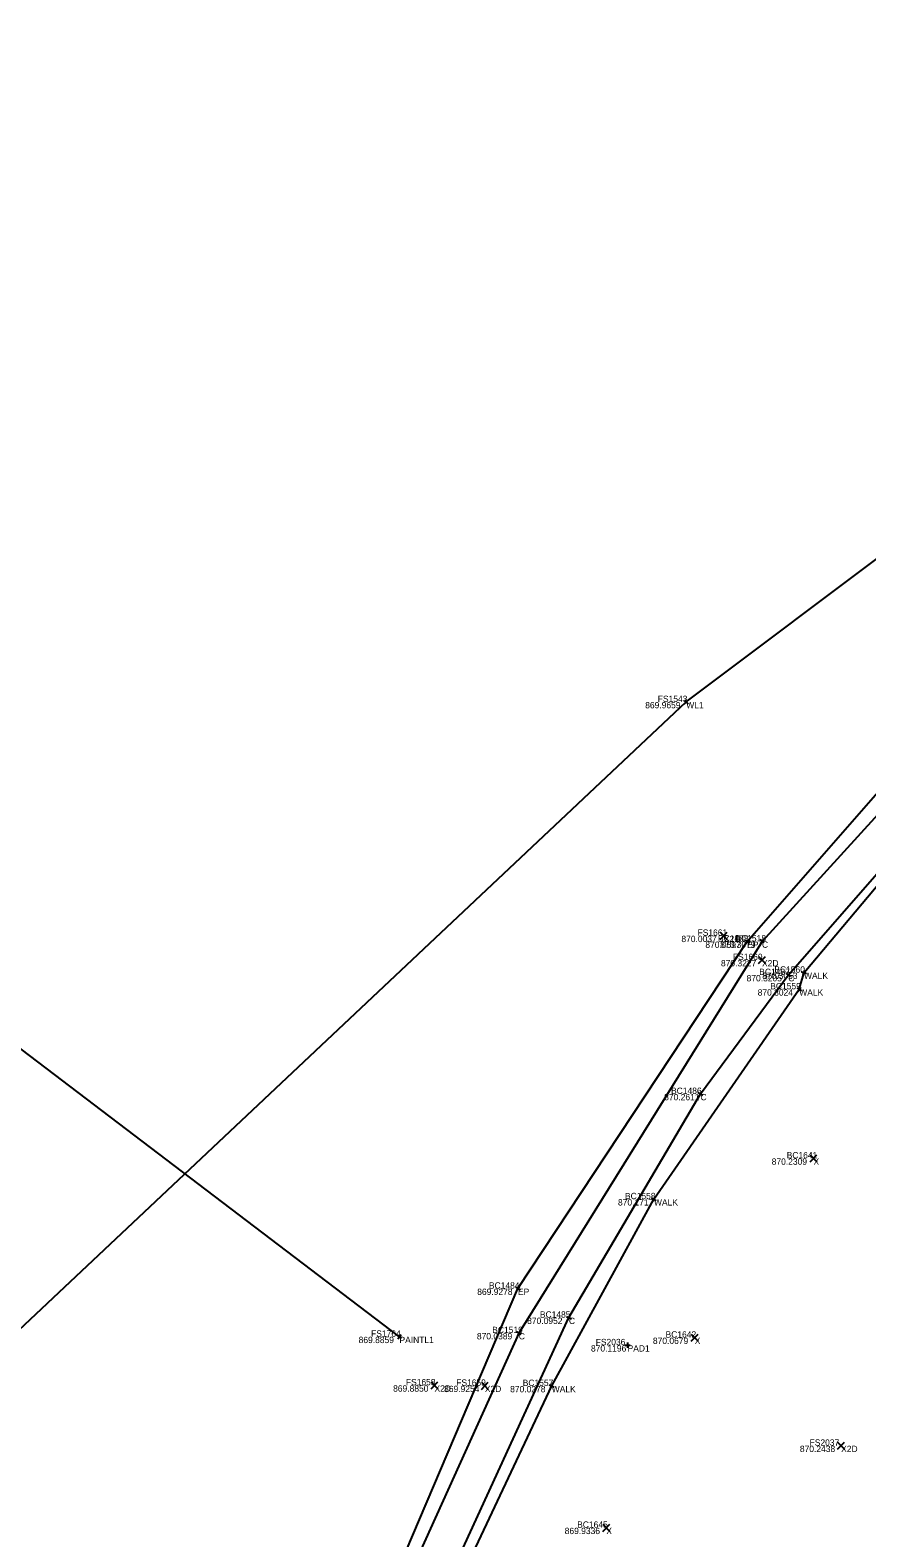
# Model space of a CAD drawing. Extents: x 1479425 to 1480294, y 379351 to 380102.
# Drawn here: x 1479693.48 to 1479701.41, y 379921.85 to 379936.13 of the extents above; entities that cross this region are included whole.
import ezdxf

# ---------------------------------------------------------------- set-up
doc = ezdxf.new("R2010")
doc.units = 0
for name, color, linetype in [('PM_X_Crosswalk', 7, 'Continuous'), ('PV_X_Curb', 7, 'Continuous'), ('PV_X_Walk', 7, 'Continuous'), ('SV_X_Random_Point', 7, 'Continuous'), ('SV_X_Shot_Marker', 7, 'Continuous'), ('SV_X_Text_Comment', 7, 'Continuous'), ('SV_X_Text_Elevation', 7, 'Continuous'), ('SV_X_Text_Name', 7, 'Continuous'), ('UT_X_Water', 7, 'Continuous')]:
    doc.layers.add(name, color=color, linetype=linetype)

msp = doc.modelspace()

# ---------------------------------------------------------------- linework, layer by layer
at = {"layer": 'PM_X_Crosswalk'}
msp.add_lwpolyline([(1479696.985, 379923.758), (1479671.854, 379942.855)], dxfattribs=at)
at = {"layer": 'PV_X_Curb'}
for points in [[(1479696.264, 379903.539), (1479695.57, 379906.746), (1479695.297, 379909.341), (1479695.174, 379911.646), (1479695.365, 379914.612), (1479695.698, 379917.667), (1479696.262, 379919.569), (1479696.976, 379921.561), (1479698.108, 379924.214), (1479700.28, 379927.501), (1479703.025, 379930.637), (1479705.95, 379933.539), (1479706.943, 379934.379), (1479708.075, 379934.808), (1479711.183, 379937.553), (1479719.99, 379942.117), (1479736.739, 379950.532), (1479753.296, 379958.795), (1479766.716, 379965.563), (1479785.836, 379974.829), (1479802.25, 379983.054), (1479831.407, 379997.252)], [(1479714.562, 379931.597), (1479714.954, 379931.846), (1479713.923, 379933.146), (1479712.281, 379934.169), (1479710.424, 379934.773), (1479708.769, 379934.79), (1479708.11, 379934.798), (1479707.065, 379934.215), (1479706.4, 379933.843), (1479705.682, 379933.059), (1479703.005, 379930.335), (1479700.421, 379927.502), (1479698.116, 379923.793), (1479697.054, 379921.447), (1479696.317, 379919.513), (1479695.811, 379917.681), (1479695.461, 379914.266), (1479695.292, 379911.66), (1479695.283, 379911.471), (1479695.51, 379908.764), (1479695.652, 379906.806)], [(1479696.734, 379903.723), (1479696.078, 379906.871), (1479695.857, 379909.367), (1479695.679, 379911.575), (1479695.63, 379911.718), (1479695.729, 379913.104), (1479695.978, 379915.675), (1479696.198, 379917.494), (1479696.642, 379919.385), (1479697.412, 379921.373), (1479698.591, 379923.939), (1479699.838, 379926.058), (1479700.67, 379927.184), (1479703.372, 379930.269), (1479706.251, 379933.059), (1479706.672, 379933.535), (1479707.045, 379933.739), (1479707.413, 379933.924), (1479708.304, 379934.333), (1479710.149, 379934.374), (1479711.615, 379933.931), (1479713.621, 379932.885), (1479714.299, 379932.035), (1479714.562, 379931.597)]]:
    msp.add_lwpolyline(points, dxfattribs=at)
at = {"layer": 'PV_X_Walk'}
msp.add_lwpolyline([(1479697.529, 379921.382), (1479698.428, 379923.292), (1479699.397, 379925.061), (1479700.774, 379927.049), (1479700.819, 379927.207), (1479702.519, 379929.228)], dxfattribs=at)
at = {"layer": 'SV_X_Random_Point'}
for p, q in [((1479700.026, 379927.522), (1479700.092, 379927.589)), ((1479700.026, 379927.589), (1479700.092, 379927.522)), ((1479700.388, 379927.293), (1479700.454, 379927.36)), ((1479700.388, 379927.36), (1479700.454, 379927.293)), ((1479700.876, 379925.414), (1479700.942, 379925.481)), ((1479700.876, 379925.481), (1479700.942, 379925.414)), ((1479699.749, 379923.717), (1479699.816, 379923.783)), ((1479699.749, 379923.783), (1479699.816, 379923.717)), ((1479697.284, 379923.264), (1479697.35, 379923.331)), ((1479697.284, 379923.331), (1479697.35, 379923.264)), ((1479697.761, 379923.26), (1479697.827, 379923.327)), ((1479697.761, 379923.327), (1479697.827, 379923.26)), ((1479701.138, 379922.693), (1479701.204, 379922.759)), ((1479701.138, 379922.759), (1479701.204, 379922.693)), ((1479698.912, 379921.915), (1479698.978, 379921.982)), ((1479698.912, 379921.982), (1479698.978, 379921.915))]:
    msp.add_line(p, q, dxfattribs=at)
at = {"layer": 'SV_X_Shot_Marker'}
for p, q in [((1479699.685, 379929.753), (1479699.721, 379929.788)), ((1479699.686, 379929.789), (1479699.72, 379929.752)), ((1479699.703, 379929.77), (1479699.703, 379929.77)), ((1479700.261, 379927.518), (1479700.299, 379927.485)), ((1479700.263, 379927.482), (1479700.296, 379927.52)), ((1479700.28, 379927.501), (1479700.28, 379927.501)), ((1479700.439, 379927.485), (1479700.402, 379927.519)), ((1479700.438, 379927.52), (1479700.404, 379927.483)), ((1479700.421, 379927.502), (1479700.421, 379927.502)), ((1479700.65, 379927.199), (1479700.69, 379927.169)), ((1479700.655, 379927.164), (1479700.685, 379927.204)), ((1479700.67, 379927.184), (1479700.67, 379927.184)), ((1479700.795, 379927.214), (1479700.843, 379927.2)), ((1479700.812, 379927.183), (1479700.826, 379927.231)), ((1479700.819, 379927.207), (1479700.819, 379927.207)), ((1479700.754, 379927.063), (1479700.795, 379927.035)), ((1479700.76, 379927.029), (1479700.789, 379927.07)), ((1479700.774, 379927.049), (1479700.774, 379927.049)), ((1479699.816, 379926.07), (1479699.86, 379926.045)), ((1479699.825, 379926.036), (1479699.851, 379926.079)), ((1479699.838, 379926.058), (1479699.838, 379926.058)), ((1479699.375, 379925.073), (1479699.419, 379925.049)), ((1479699.385, 379925.039), (1479699.409, 379925.083)), ((1479699.397, 379925.061), (1479699.397, 379925.061)), ((1479698.087, 379924.227), (1479698.129, 379924.2)), ((1479698.094, 379924.193), (1479698.122, 379924.234)), ((1479698.108, 379924.214), (1479698.108, 379924.214)), ((1479698.568, 379923.949), (1479698.614, 379923.928)), ((1479698.581, 379923.916), (1479698.602, 379923.961)), ((1479698.591, 379923.939), (1479698.591, 379923.939)), ((1479697.005, 379923.743), (1479696.965, 379923.773)), ((1479696.97, 379923.738), (1479697, 379923.778)), ((1479696.985, 379923.758), (1479696.985, 379923.758)), ((1479698.137, 379923.779), (1479698.095, 379923.806)), ((1479698.129, 379923.814), (1479698.103, 379923.771)), ((1479698.116, 379923.793), (1479698.116, 379923.793)), ((1479699.122, 379923.678), (1479699.172, 379923.678)), ((1479699.147, 379923.703), (1479699.147, 379923.653)), ((1479699.147, 379923.678), (1479699.147, 379923.678)), ((1479698.405, 379923.303), (1479698.45, 379923.282)), ((1479698.417, 379923.27), (1479698.438, 379923.315)), ((1479698.428, 379923.292), (1479698.428, 379923.292))]:
    msp.add_line(p, q, dxfattribs=at)
at = {"layer": 'UT_X_Water'}
msp.add_lwpolyline([(1479653.917, 379883.075), (1479656.453, 379885.901), (1479682.649, 379913.582), (1479686.182, 379917.14), (1479686.736, 379917.656), (1479692.788, 379923.268), (1479699.703, 379929.77), (1479707.876, 379935.91), (1479714.6, 379939.488), (1479720.618, 379942.792), (1479734.686, 379951.003), (1479759.021, 379964.62), (1479771.505, 379971.304), (1479799.27, 379984.838)], dxfattribs=at)

# ---------------------------------------------------------------- texts
at = {"layer": 'SV_X_Text_Comment'}
for s, p in [('WL1', (1479699.703, 379929.71)), ('X2D', (1479700.059, 379927.496)), ('EP', (1479700.28, 379927.441)), ('C', (1479700.421, 379927.442)), ('X2D', (1479700.421, 379927.266)), ('C', (1479700.67, 379927.124)), ('WALK', (1479700.819, 379927.147)), ('WALK', (1479700.774, 379926.989)), ('C', (1479699.838, 379925.998)), ('X', (1479700.909, 379925.387)), ('WALK', (1479699.397, 379925.001)), ('EP', (1479698.108, 379924.154)), ('C', (1479698.591, 379923.879)), ('PAINTL1', (1479696.985, 379923.698)), ('C', (1479698.116, 379923.733)), ('X', (1479699.783, 379923.69)), ('PAD1', (1479699.147, 379923.618)), ('X2D', (1479697.317, 379923.238)), ('X2D', (1479697.794, 379923.234)), ('WALK', (1479698.428, 379923.232)), ('X2D', (1479701.171, 379922.666)), ('X', (1479698.945, 379921.889))]:
    msp.add_text(s, height=0.06, dxfattribs=at).set_placement(p)
at = {"layer": 'SV_X_Text_Elevation'}
for s, p in [('869.9659', (1479699.314, 379929.71)), ('870.0037', (1479699.657, 379927.496)), ('870.0597', (1479699.884, 379927.441)), ('870.3079', (1479700.025, 379927.442)), ('870.3227', (1479700.032, 379927.266)), ('870.3205', (1479700.275, 379927.124)), ('870.3053', (1479700.423, 379927.147)), ('870.3024', (1479700.38, 379926.989)), ('870.2611', (1479699.494, 379925.998)), ('870.2309', (1479700.513, 379925.387)), ('870.1717', (1479699.056, 379925.001)), ('869.9278', (1479697.722, 379924.154)), ('870.0952', (1479698.195, 379923.879)), ('869.8859', (1479696.598, 379923.698)), ('870.0389', (1479697.719, 379923.733)), ('870.0679', (1479699.387, 379923.69)), ('870.1196', (1479698.8, 379923.618)), ('869.8850', (1479696.925, 379923.238)), ('869.9254', (1479697.408, 379923.234)), ('870.0278', (1479698.034, 379923.232)), ('870.2438', (1479700.78, 379922.666)), ('869.9336', (1479698.551, 379921.889))]:
    msp.add_text(s, height=0.06, dxfattribs=at).set_placement(p)
at = {"layer": 'SV_X_Text_Name'}
for s, p in [('FS1543', (1479699.433, 379929.77)), ('FS1661', (1479699.81, 379927.556)), ('BC1488', (1479700.004, 379927.501)), ('BC1518', (1479700.169, 379927.502)), ('FS1660', (1479700.145, 379927.326)), ('BC1487', (1479700.395, 379927.184)), ('BC1560', (1479700.538, 379927.207)), ('BC1559', (1479700.499, 379927.049)), ('BC1486', (1479699.559, 379926.058)), ('BC1641', (1479700.655, 379925.447)), ('BC1558', (1479699.122, 379925.061)), ('BC1484', (1479697.833, 379924.214)), ('BC1485', (1479698.316, 379923.939)), ('FS1764', (1479696.716, 379923.758)), ('BC1519', (1479697.864, 379923.793)), ('BC1642', (1479699.507, 379923.75)), ('FS2036', (1479698.845, 379923.678)), ('FS1658', (1479697.046, 379923.298)), ('FS1659', (1479697.523, 379923.294)), ('BC1557', (1479698.153, 379923.292)), ('FS2037', (1479700.872, 379922.726)), ('BC1645', (1479698.669, 379921.949))]:
    msp.add_text(s, height=0.06, dxfattribs=at).set_placement(p)

doc.saveas('drawing.dxf')
